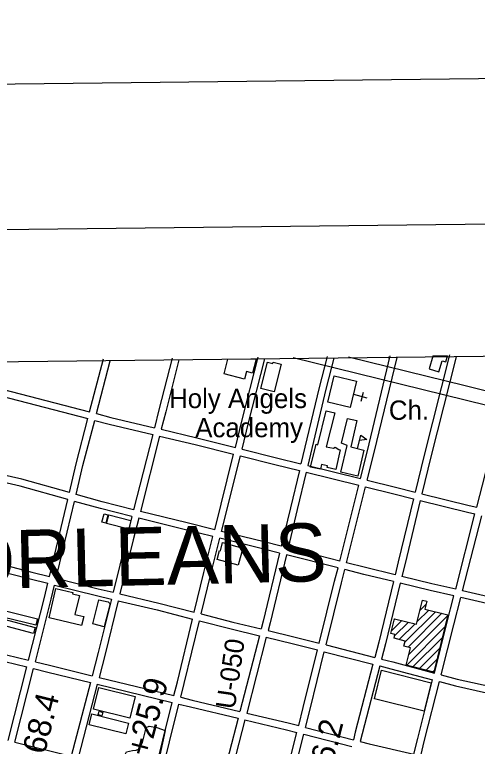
# Model space of a CAD drawing. Extents: x 3677843 to 3715951, y 511991 to 537744.
# Drawn here: x 3689113 to 3691100, y 534017 to 537161 of the extents above; entities that cross this region are included whole.
import ezdxf

# ---------------------------------------------------------------- set-up
doc = ezdxf.new("R2010")
doc.units = 0
for name, color, linetype in [('G-ANNO-NPLT', 7, 'Continuous'), ('V-ANNO-SYMB', 7, 'Continuous'), ('V-BLDG-IDEN', 7, 'Continuous'), ('V-BLDG-OTLN', 7, 'Continuous'), ('V-GRID-FRAM', 7, 'Continuous'), ('V-RIVR-RANG-IDEN', 7, 'Continuous'), ('V-ROAD-CNTR', 7, 'Continuous'), ('V-SITE-OTLN', 7, 'Continuous'), ('V-SITE-OTLN-IDEN', 7, 'Continuous'), ('V-SITE-VEGE', 7, 'Continuous'), ('V-SURV-IDEN', 7, 'Continuous'), ('V-TOPO-GNAM-IDEN', 7, 'Continuous')]:
    doc.layers.add(name, color=color, linetype=linetype)

msp = doc.modelspace()

# ---------------------------------------------------------------- linework, layer by layer
at = {"layer": 'G-ANNO-NPLT'}
msp.add_lwpolyline([(3678703.9, 512574.2), (3715368.2, 512995.5), (3715090.5, 537160.6), (3678426.3, 536739.3)], close=True, dxfattribs=at)
at = {"layer": 'V-ANNO-SYMB'}
msp.add_lwpolyline([(3681446.7, 513230.8), (3714527.7, 513611), (3714264.4, 536526), (3681183.4, 536145.9), (3681446.7, 513230.8)], dxfattribs=at)
at = {"layer": 'V-BLDG-OTLN'}
for p, q in [((3690716.3, 535688.4), (3690719.8, 535688.4)), ((3690719.6, 535687.6), (3690716.3, 535688.4)), ((3690719.8, 535688.4), (3690719.6, 535687.6)), ((3690971.6, 535694.6), (3690908.7, 535693.9)), ((3690012.4, 535617.6), (3690028.4, 535680.5)), ((3690028.4, 535680.5), (3690145.8, 535681.9)), ((3690149.6, 535680.9), (3690134.2, 535620.8)), ((3690145.8, 535681.9), (3690149.6, 535680.9)), ((3690108.8, 535627.3), (3690100.6, 535595.1)), ((3690134.2, 535620.8), (3690108.8, 535627.3)), ((3690100.6, 535595.1), (3690012.4, 535617.6)), ((3690584.7, 535295.8), (3690599.1, 535354)), ((3690853.2, 534600.5), (3690878.9, 534626.2)), ((3690788.9, 534465.5), (3690919.4, 534596)), ((3690802.3, 534443.5), (3690947.8, 534589)), ((3690841.7, 534553.6), (3690891, 534602.9)), ((3690731.7, 534514.3), (3690775.6, 534558.2)), ((3690743.2, 534561.2), (3690747.2, 534565.2)), ((3690805.7, 534411.5), (3690972, 534577.8)), ((3690744.3, 534491.6), (3690804, 534551.3)), ((3690764.3, 534476.2), (3690832.4, 534544.3)), ((3690795, 534365.5), (3690960.5, 534531)), ((3690823.4, 534358.5), (3690949, 534484.2)), ((3690851.8, 534351.6), (3690937.6, 534437.3)), ((3690880.2, 534344.6), (3690926.1, 534390.5)), ((3690908.6, 534337.7), (3690914.6, 534343.7))]:
    msp.add_line(p, q, dxfattribs=at)
for points in [[(3690892.8, 535639), (3690934.6, 535626.9), (3690948.2, 535673.7), (3690964.2, 535669), (3690971.6, 535694.6)], [(3690908.7, 535693.9), (3690892.8, 535639)]]:
    msp.add_lwpolyline(points, dxfattribs=at)
for points in [[(3690169.9, 535554.9), (3690198.3, 535667.4), (3690222, 535661.4), (3690223.6, 535667.6), (3690257, 535659.2), (3690227.1, 535540.4)], [(3690488.4, 535450.1), (3690450.2, 535304.1), (3690482.1, 535297.8), (3690489.4, 535302.9), (3690504.7, 535293), (3690510.1, 535291.1), (3690491.9, 535206.7), (3690454.5, 535214.7), (3690456.3, 535222.8), (3690431.3, 535228.2), (3690426.8, 535207.5), (3690384, 535216.7), (3690408.3, 535315.7), (3690415.3, 535313.2), (3690450.7, 535458.9)], [(3690517, 535319.5), (3690542, 535426.2), (3690582.8, 535416.6), (3690556.4, 535303.7), (3690612.9, 535290.5), (3690586.5, 535177.7), (3690513.1, 535194.8), (3690541, 535310.4)], [(3690599.1, 535354), (3690625.5, 535335.6), (3690593.6, 535331.6)], [(3689513.5, 535012.4), (3689504.3, 534976.3), (3689487.7, 534980.6), (3689496.8, 535016.6)], [(3689602.9, 534950.9), (3689507.7, 534975), (3689516.9, 535011.4), (3689612.1, 534987.2)], [(3690092.9, 534869.2), (3690073.2, 534795.7), (3689982.7, 534819.9), (3689993.1, 534858.8), (3689996.5, 534857.9), (3690005.7, 534892.5)], [(3689260.9, 534569.3), (3689290.2, 534695.1), (3689362.9, 534678.2), (3689361.7, 534672.7), (3689391.3, 534665.8), (3689372.2, 534583.7), (3689410.2, 534574.8), (3689400.6, 534536.8)], [(3689515.3, 534637.6), (3689522.9, 534629.5), (3689498.1, 534530.3), (3689448.4, 534543.3), (3689474.4, 534647.3)], [(3690973.2, 534582.8), (3690912.9, 534336.6), (3690794.4, 534365.6), (3690812.9, 534440.9), (3690784.6, 534447.8), (3690790, 534469.9), (3690741.9, 534481.7), (3690745.8, 534497.6), (3690728.6, 534501.8), (3690744.4, 534565.9), (3690839, 534542.7), (3690864.4, 534646), (3690882.7, 534641.5), (3690874.3, 534607)], [(3689204.5, 534538.4), (3689067.9, 534571.7), (3689074.5, 534599), (3689211.2, 534565.8)], [(3689194, 534502.4), (3689060.1, 534537.7), (3689066.9, 534563.5), (3689200.8, 534528.2)], [(3690871.1, 534168.6), (3690658.1, 534221.6), (3690688.6, 534344.1), (3690901.6, 534291)], [(3689607.8, 534138.2), (3689451.5, 534177), (3689474.6, 534270.2), (3689630.9, 534231.4)], [(3689590.3, 534070.8), (3689433.3, 534109.6), (3689444.9, 534156.5), (3689601.9, 534117.7)], [(3689491.9, 534163.3), (3689487.4, 534148.4), (3689471.1, 534153.4), (3689475.7, 534168.3)]]:
    msp.add_lwpolyline(points, close=True, dxfattribs=at)
at = {"layer": 'V-GRID-FRAM'}
msp.add_lwpolyline([(3681899.6, 535587.1), (3713561.2, 535950.9), (3713778.1, 517769.3), (3682100.6, 517405.3), (3681899.6, 535587.1)], dxfattribs=at)
at = {"layer": 'V-ROAD-CNTR'}
for points in [[(3690060.7, 535301.6), (3690088.8, 535413.9), (3690158.3, 535689.1)], [(3690454.9, 535692.6), (3690420.5, 535559.1), (3690342.6, 535231.2)], [(3693205.9, 534998.8), (3692998.1, 535077.3), (3692752.7, 535138.7), (3691047.7, 535565.6), (3690546.4, 535689.7)], [(3690597.9, 535168), (3690627.8, 535287.3), (3690725.7, 535695.4)], [(3690627, 535160.8), (3690657, 535280.1), (3690754.9, 535688.4)], [(3690980.2, 535698.6), (3690871.2, 535268.9), (3690832.7, 535110)], [(3691009.2, 535691.2), (3690900.3, 535261.7), (3690861.8, 535102.8)], [(3691096.9, 535044.7), (3691134.1, 535189.8), (3691258.6, 535701.6)], [(3689435.2, 535454.3), (3689494, 535681.5)], [(3689464.3, 535446.7), (3689523, 535674)], [(3689789.8, 535684.9), (3689732.5, 535462.5), (3689713.2, 535386.2)], [(3689818.8, 535677.4), (3689761.6, 535455), (3689742.4, 535379.3)], [(3690089.8, 535294.3), (3690117.9, 535406.6), (3690187.4, 535681.8)], [(3693205.9, 534998.8), (3692975.1, 535023.9), (3691698, 535344.1), (3690309.3, 535687)], [(3690483.9, 535685.1), (3690449.6, 535551.9), (3690371.7, 535224)], [(3688910.7, 535589.5), (3688986.3, 535571), (3689435.2, 535454.3)], [(3688903.2, 535560.5), (3688979, 535541.9), (3689427.7, 535425.3)], [(3689464.3, 535446.7), (3689526.8, 535430.5), (3689713.2, 535386.2)], [(3689348.1, 535107.3), (3689377.5, 535230.9), (3689427.7, 535425.3)], [(3689377, 535099.2), (3689406.6, 535223.7), (3689456.8, 535417.7)], [(3689456.8, 535417.7), (3689519.6, 535401.4), (3689705.8, 535357.2)], [(3689742.4, 535379.3), (3689895.8, 535342.9), (3690060.7, 535301.6)], [(3689705.8, 535357.2), (3689624, 535034.2)], [(3689735, 535350.2), (3689653.1, 535027)], [(3689735, 535350.2), (3689888.7, 535313.7), (3690053.4, 535272.5)], [(3690089.8, 535294.3), (3690237.2, 535257.3), (3690342.6, 535231.2)], [(3689972, 534947.9), (3690053.4, 535272.5)], [(3690001.1, 534940.8), (3690082.5, 535265.2)], [(3690082.5, 535265.2), (3690229.9, 535228.2), (3690335.7, 535202.1)], [(3689348.1, 535107.3), (3689143.5, 535164.6), (3688819.7, 535238)], [(3690371.7, 535224), (3690597.9, 535168)], [(3689341.1, 535078.1), (3689136.2, 535135.5), (3688812.2, 535209)], [(3690335.7, 535202.1), (3690297.6, 535041.9), (3690258, 534877.1)], [(3690364.8, 535194.8), (3690326.8, 535035), (3690287, 534869.7)], [(3690364.8, 535194.8), (3690590.6, 535138.9)], [(3690627, 535160.8), (3690748.5, 535130.7), (3690832.7, 535110)], [(3690508.9, 534813.5), (3690590.6, 535138.9)], [(3690538, 534806.2), (3690619.7, 535131.7)], [(3690619.7, 535131.7), (3690741.3, 535101.6), (3690825.6, 535080.8)], [(3689624, 535034.2), (3689489.3, 535067.8), (3689377, 535099.2)], [(3690861.8, 535102.8), (3691065.3, 535052.6), (3691096.9, 535044.7)], [(3689262.3, 534747), (3689341.1, 535078.1)], [(3689291.4, 534739.7), (3689370, 535070)], [(3689616.6, 535005.2), (3689481.6, 535038.8), (3689370, 535070)], [(3690825.6, 535080.8), (3690760.1, 534810.3), (3690746.5, 534754.5)], [(3690854.8, 535073.6), (3690789.3, 534803.2), (3690775.7, 534747.3)], [(3690854.8, 535073.6), (3691058, 535023.5), (3691089.5, 535015.6)], [(3689616.6, 535005.2), (3689592.8, 534911.3), (3689535.9, 534679.2)], [(3689645.7, 534997.9), (3689622, 534904.1), (3689565.1, 534672.4)], [(3689964.7, 534918.8), (3689846.3, 534947.9), (3689645.7, 534997.9)], [(3689972, 534947.9), (3689853.5, 534977.1), (3689653.1, 535027)], [(3691006.7, 534692.4), (3691089.5, 535015.6)], [(3691036, 534685.7), (3691118.5, 535008.3)], [(3690258, 534877.1), (3690184.7, 534895.6), (3690001.1, 534940.8)], [(3689884.4, 534593.7), (3689925.8, 534763.8), (3689964.7, 534918.8)], [(3689913.5, 534586.2), (3689954.9, 534756.6), (3689993.8, 534911.7)], [(3690250.9, 534847.9), (3690177.5, 534866.5), (3689993.8, 534911.7)], [(3688722.5, 534852.7), (3688779.1, 534838.7), (3689180.1, 534736.7), (3689255.3, 534717.8)], [(3690250.9, 534847.9), (3690180.7, 534555.9), (3690171.9, 534521.9)], [(3690280, 534840.5), (3690209.8, 534548.7), (3690201, 534514.9)], [(3690501.6, 534784.5), (3690280, 534840.5)], [(3690508.9, 534813.5), (3690287, 534869.7)], [(3689038.2, 534803.7), (3689187.4, 534765.8), (3689262.3, 534747)], [(3690420.9, 534460.6), (3690487.1, 534726.9), (3690501.6, 534784.5)], [(3690450, 534453.2), (3690516.2, 534719.6), (3690530.7, 534777.1)], [(3690739.5, 534725.3), (3690612.8, 534756.3), (3690530.7, 534777.1)], [(3690746.5, 534754.5), (3690620.1, 534785.4), (3690538, 534806.2)], [(3691006.7, 534692.4), (3690904, 534715.9), (3690775.7, 534747.3)], [(3689172.8, 534387.9), (3689240.9, 534657), (3689255.3, 534717.8)], [(3689291.4, 534739.7), (3689471.7, 534694.4), (3689535.9, 534679.2)], [(3690739.5, 534725.3), (3690676.2, 534465), (3690659.2, 534399.7)], [(3690768.6, 534718.2), (3690705.2, 534457.7), (3690688.3, 534392.3)], [(3690999.3, 534663.4), (3690897.1, 534686.7), (3690768.6, 534718.2)], [(3689202, 534380.8), (3689270, 534649.8), (3689284.4, 534710.5)], [(3689284.4, 534710.5), (3689464.7, 534665.2), (3689528.8, 534650.1)], [(3691277.8, 534627), (3691166.6, 534655.9), (3691036, 534685.7)], [(3689528.8, 534650.1), (3689472.4, 534420.1), (3689446.6, 534321.1)], [(3689565.1, 534672.4), (3689732.7, 534632.9), (3689884.4, 534593.7)], [(3690915.2, 534332.6), (3690969.4, 534546.7), (3690999.3, 534663.4)], [(3690944.2, 534324.9), (3690998.5, 534539.3), (3691028.5, 534656.7)], [(3691270.8, 534597.8), (3691159.4, 534626.7), (3691028.5, 534656.7)], [(3689558, 534643.2), (3689501.5, 534412.8), (3689475.7, 534313.9)], [(3689558, 534643.2), (3689725.5, 534603.7), (3689877.4, 534564.5)], [(3689797, 534235.3), (3689811.8, 534294.6), (3689877.4, 534564.5)], [(3689826.1, 534228.1), (3689840.9, 534287.5), (3689906.4, 534557)], [(3689906.4, 534557), (3690042.6, 534521.8), (3690164.4, 534492.8)], [(3689913.5, 534586.2), (3690049.8, 534550.9), (3690171.9, 534521.9)], [(3688639.8, 534518.8), (3688699.5, 534502.9), (3689172.8, 534387.9)], [(3690201, 534514.9), (3690311.3, 534488.6), (3690420.9, 534460.6)], [(3688632.4, 534489.7), (3688692.1, 534473.8), (3689165.5, 534358.8)], [(3690164.4, 534492.8), (3690080.3, 534167.4)], [(3690193.5, 534485.9), (3690109.5, 534160.5)], [(3690193.5, 534485.9), (3690304.1, 534459.5), (3690413.7, 534431.5)], [(3690332.7, 534106.5), (3690352.2, 534184.2), (3690413.7, 534431.5)], [(3690450, 534453.2), (3690659.2, 534399.7)], [(3690361.7, 534099.1), (3690381.3, 534177), (3690442.7, 534424.1)], [(3690442.7, 534424.1), (3690651.6, 534370.7)], [(3689202, 534380.8), (3689263.3, 534365.9), (3689446.6, 534321.1)], [(3690651.6, 534370.7), (3690575.6, 534078.1), (3690567.8, 534046)], [(3690688.3, 534392.3), (3690736.5, 534380), (3690915.2, 534332.6)], [(3689085.5, 534042.7), (3689165.5, 534358.8)], [(3689114.6, 534035.4), (3689194.6, 534351.8)], [(3689194.6, 534351.8), (3689256.2, 534336.8), (3689439, 534292)], [(3690680.7, 534363.3), (3690604.7, 534070.8), (3690596.8, 534038.5)], [(3690680.7, 534363.3), (3690728.9, 534350.9), (3690907.8, 534303.5)], [(3689475.7, 534313.9), (3689797, 534235.3)], [(3690944.2, 534324.9), (3691013, 534306.7), (3691190.9, 534266.8)], [(3689439, 534292), (3689356.2, 533974.8)], [(3689468.1, 534284.9), (3689385.3, 533967.5)], [(3689468.1, 534284.9), (3689789.7, 534206.2)], [(3690827.4, 533983.5), (3690844.1, 534051.9), (3690907.8, 534303.5)], [(3690856.6, 533976.7), (3690873.2, 534044.7), (3690936.8, 534295.8)], [(3690936.8, 534295.8), (3691005.9, 534277.5), (3691183.9, 534237.7)], [(3689826.1, 534228.1), (3689874.7, 534216.2), (3690080.3, 534167.4)], [(3689709, 533882.7), (3689789.7, 534206.2)], [(3689738, 533875.1), (3689818.8, 534199)], [(3689818.8, 534199), (3689867.7, 534187.1), (3690072.8, 534138.3)], [(3690109.5, 534160.5), (3690287.3, 534118.2), (3690332.7, 534106.5)], [(3690072.8, 534138.3), (3690034.2, 533989), (3689982.1, 533816.8)], [(3690102, 534131.4), (3690063.1, 533980.9), (3690011.4, 533809.9)], [(3690102, 534131.4), (3690280.1, 534089.1), (3690325.4, 534077.4)], [(3690361.7, 534099.1), (3690567.8, 534046)], [(3690243.7, 533752.2), (3690325.4, 534077.4)], [(3690272.7, 533744.6), (3690354.4, 534070)], [(3690354.4, 534070), (3690560.6, 534016.9)], [(3689114.6, 534035.4), (3689356.2, 533974.8)], [(3690596.8, 534038.5), (3690634.8, 534028.8), (3690827.4, 533983.5)]]:
    msp.add_lwpolyline(points, dxfattribs=at)
at = {"layer": 'V-SITE-OTLN'}
for p, q in [((3690601.4, 535500.4), (3690611.4, 535539.1)), ((3690567.7, 535529.8), (3690625.8, 535514.7))]:
    msp.add_line(p, q, dxfattribs=at)
msp.add_lwpolyline([(3690457.3, 535496.5), (3690484.7, 535609.4), (3690580.4, 535586.2), (3690553.1, 535473.3)], close=True, dxfattribs=at)
at = {"layer": 'V-SITE-VEGE'}
msp.add_lwpolyline([(3689760, 534086), (3689721, 533907), (3689715.7, 533894), (3689702.1, 533893.2), (3689693.2, 533896.5), (3689686.3, 533910), (3689687.5, 533924.3), (3689684.7, 533939.2), (3689677.8, 533947.3), (3689662.8, 533953.2), (3689630.1, 533958.4), (3689608.3, 533964.3), (3689590.6, 533972.9), (3689587.1, 533982.4), (3689593.8, 533994), (3689619.5, 533999), (3689634.5, 534001.2), (3689648, 534007.4), (3689662.7, 534034.1), (3689675.1, 534085.2), (3689677.7, 534098.1), (3689691.2, 534103.7), (3689723.9, 534098.5)], close=True, dxfattribs=at)

# ---------------------------------------------------------------- texts
at = {"layer": 'V-BLDG-IDEN'}
for s, p in [('Holy Angels', (3689776.1, 535470.5)), ('Academy', (3689888.5, 535345.3))]:
    msp.add_text(s, height=83, dxfattribs=at).set_placement(p)
at = {"layer": 'V-RIVR-RANG-IDEN'}
msp.add_text('U-050', height=83, rotation=81.7553, dxfattribs=at).set_placement((3690058.2, 534174.1))
at = {"layer": 'V-SITE-OTLN-IDEN'}
msp.add_text('Ch.', height=83, dxfattribs=at).set_placement((3690719.7, 535420.2))
at = {"layer": 'V-SURV-IDEN'}
for s, rotation, p in [('   549+25.9   ', 75.3575, (3689603.4, 533645.2)), ('   545+68.4   ', 75.9182, (3689141.9, 533578.9)), ('   559+16.2   ', 75.7018, (3690359.3, 533466.3))]:
    msp.add_text(s, height=100, rotation=rotation, dxfattribs=at).set_placement(p)
at = {"layer": 'V-TOPO-GNAM-IDEN'}
msp.add_text('ORLEANS', height=250, rotation=1.3443, dxfattribs=at).set_placement((3688858.3, 534690.4))

doc.saveas('drawing.dxf')
